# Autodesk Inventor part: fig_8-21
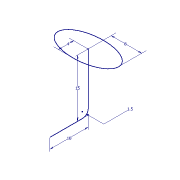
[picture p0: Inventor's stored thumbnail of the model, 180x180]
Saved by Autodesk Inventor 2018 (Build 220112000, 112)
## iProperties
Created: 2013-07
Part Number: fig_8-21
Material: Generic
Document SubType Name: Modeling
Designer: CADCIM
Density: 1 g/cm^3
Appearance: Default
Author: CADCIM
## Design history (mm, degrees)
sketch "Sketch1" dims "d0" = 8, "d1" = 4
  geometry: 2 further points; 1 other entity
  constraints: 1 coincident, 2 other
sketch "Sketch2"
  geometry: L1 (0, 0)-(0, -13.5); L2 (-1.5, -15)-(-10, -15); A1 r 1.5 centre (-1.5, -13.5) between (-1.5, -15) and (0, -13.5); 1 further point
  constraints: 4 end point, 2 point on circle, 2 point on line, 2 tangent, 1 centre point, 1 perpendicular, 1 vertical
  dimensions: "d2" = 15 distance of L1.start point (0, -15); "d3" = 10 distance of point (0, -15) L2.end; "d4" = 1.5 radius of A1
